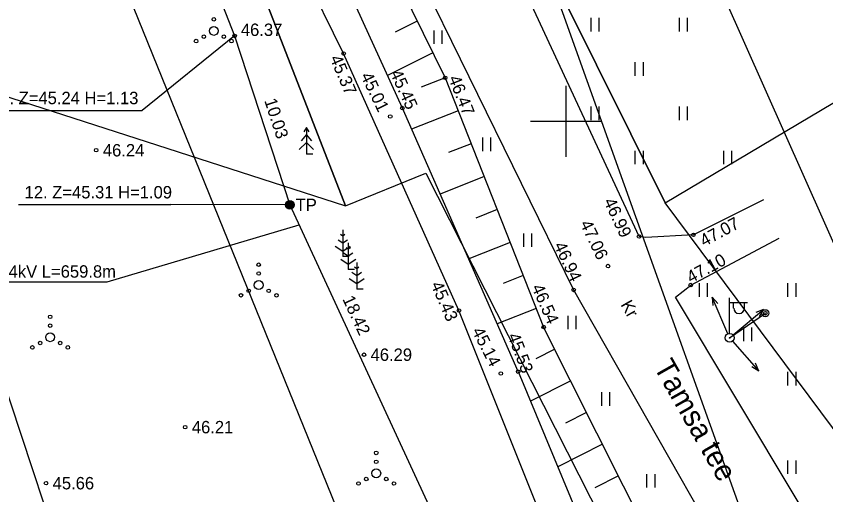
# Model space of a CAD drawing. Extents: x 642747 to 644424, y 6457048 to 6458238.
# Drawn here: x 644068.96 to 644114.68, y 6457678.92 to 6457705.93 of the extents above; entities that cross this region are included whole.
import ezdxf

# ---------------------------------------------------------------- set-up
doc = ezdxf.new("R2010")
doc.units = 0
for name, color, linetype in [('ABIJOONIS', 7, 'Continuous'), ('HALJASTUS', 7, 'Continuous'), ('JOONSIDE', 7, 'Continuous'), ('KOORDPUNKT', 7, 'Continuous'), ('KORGUS', 7, 'Continuous'), ('KPKAABEL', 7, 'Continuous'), ('KPOHULIIN', 7, 'Continuous'), ('MOOTPIIR', 7, 'Continuous'), ('MPOHULIIN', 7, 'Continuous'), ('PIIR', 7, 'Continuous'), ('POST', 7, 'Continuous'), ('PUU', 7, 'Continuous'), ('RELJEEF', 7, 'Continuous'), ('TEE', 7, 'Continuous'), ('VEEKOGU', 7, 'Continuous'), ('VORK', 7, 'Continuous'), ('VORMISTUS', 7, 'Continuous')]:
    doc.layers.add(name, color=color, linetype=linetype)

msp = doc.modelspace()

# ---------------------------------------------------------------- linework, layer by layer
at = {"layer": 'ABIJOONIS'}
msp.add_lwpolyline([(644048.392, 6457690.932), (644074.092, 6457690.932), (644084.942, 6457694.151)], dxfattribs=at)
at = {"layer": 'HALJASTUS'}
for p, q in [((644101.406, 6457705.833), (644101.406, 6457705.072)), ((644101.861, 6457705.833), (644101.861, 6457705.072)), ((644106.406, 6457705.833), (644106.406, 6457705.072)), ((644106.861, 6457705.833), (644106.861, 6457705.072)), ((644092.542, 6457705.127), (644092.542, 6457704.366)), ((644092.997, 6457705.127), (644092.997, 6457704.366)), ((644103.906, 6457703.333), (644103.906, 6457702.572)), ((644104.361, 6457703.333), (644104.361, 6457702.572)), ((644101.406, 6457700.833), (644101.406, 6457700.072)), ((644101.861, 6457700.833), (644101.861, 6457700.072)), ((644106.406, 6457700.833), (644106.406, 6457700.072)), ((644106.861, 6457700.833), (644106.861, 6457700.072)), ((644095.293, 6457699.079), (644095.293, 6457698.318)), ((644095.748, 6457699.079), (644095.748, 6457698.318)), ((644103.906, 6457698.333), (644103.906, 6457697.572)), ((644104.361, 6457698.333), (644104.361, 6457697.572)), ((644108.906, 6457698.333), (644108.906, 6457697.572)), ((644109.361, 6457698.333), (644109.361, 6457697.572)), ((644097.602, 6457693.676), (644097.602, 6457692.915)), ((644098.057, 6457693.676), (644098.057, 6457692.915)), ((644107.529, 6457690.856), (644107.529, 6457690.095)), ((644107.984, 6457690.856), (644107.984, 6457690.095)), ((644112.529, 6457690.856), (644112.529, 6457690.095)), ((644112.984, 6457690.856), (644112.984, 6457690.095)), ((644100.115, 6457689.021), (644100.115, 6457688.26)), ((644100.57, 6457689.021), (644100.57, 6457688.26)), ((644110.029, 6457688.356), (644110.029, 6457687.595)), ((644110.484, 6457688.356), (644110.484, 6457687.595)), ((644112.529, 6457685.856), (644112.529, 6457685.095)), ((644112.984, 6457685.856), (644112.984, 6457685.095)), ((644102.017, 6457684.706), (644102.017, 6457683.945)), ((644102.472, 6457684.706), (644102.472, 6457683.945)), ((644112.529, 6457680.856), (644112.529, 6457680.095)), ((644112.984, 6457680.856), (644112.984, 6457680.095)), ((644104.564, 6457680.085), (644104.564, 6457679.324)), ((644105.019, 6457680.085), (644105.019, 6457679.324))]:
    msp.add_line(p, q, dxfattribs=at)
for centre, radius in [((644080.121, 6457705.751), 0.1), ((644080.121, 6457705.101), 0.25), ((644079.121, 6457704.526), 0.1), ((644079.556, 6457704.776), 0.1), ((644080.686, 6457704.776), 0.1), ((644081.121, 6457704.526), 0.1), ((644082.659, 6457691.906), 0.1), ((644082.659, 6457691.406), 0.1), ((644082.659, 6457690.756), 0.25), ((644082.094, 6457690.431), 0.1), ((644083.224, 6457690.431), 0.1), ((644081.659, 6457690.181), 0.1), ((644083.659, 6457690.181), 0.1), ((644070.877, 6457688.962), 0.1), ((644070.877, 6457688.462), 0.1), ((644070.877, 6457687.812), 0.25), ((644069.877, 6457687.237), 0.1), ((644070.312, 6457687.487), 0.1), ((644071.442, 6457687.487), 0.1), ((644071.877, 6457687.237), 0.1), ((644089.295, 6457681.283), 0.1), ((644089.295, 6457680.783), 0.1), ((644089.295, 6457680.133), 0.25), ((644088.73, 6457679.808), 0.1), ((644089.86, 6457679.808), 0.1), ((644088.295, 6457679.558), 0.1), ((644090.295, 6457679.558), 0.1)]:
    msp.add_circle(centre, radius, dxfattribs=at)
at = {"layer": 'KOORDPUNKT'}
for p, q in [((644081.299, 6457704.816), (644076.077, 6457700.616)), ((644067.187, 6457700.616), (644076.077, 6457700.616)), ((644069.084, 6457695.297), (644077.694, 6457695.297)), ((644084.417, 6457695.285), (644077.694, 6457695.297))]:
    msp.add_line(p, q, dxfattribs=at)
for points in [[(644081.299, 6457704.816), (644081.299, 6457704.816), (644081.299, 6457704.816)], [(644084.417, 6457695.285), (644084.417, 6457695.285), (644084.417, 6457695.285)]]:
    msp.add_lwpolyline(points, dxfattribs=at)
at = {"layer": 'KORGUS'}
for centre in [(644081.299, 6457704.816), (644087.455, 6457703.827), (644093.19, 6457702.456), (644090.771, 6457700.745), (644090.086, 6457700.27), (644073.48, 6457698.367), (644104.136, 6457693.495), (644107.203, 6457693.592), (644102.385, 6457691.828), (644107.056, 6457690.755), (644100.441, 6457690.483), (644093.965, 6457689.322), (644111.269, 6457689.166), (644098.75, 6457688.389), (644088.6, 6457686.827), (644096.33, 6457685.764), (644097.313, 6457685.871), (644078.505, 6457682.738), (644070.645, 6457679.575)]:
    msp.add_circle(centre, 0.1, dxfattribs=at)
at = {"layer": 'KPKAABEL'}
msp.add_lwpolyline([(644063.341, 6457736.874), (644063.814, 6457738.243), (644064.085, 6457738.786), (644069.675, 6457740.685), (644070.251, 6457740.516), (644070.657, 6457739.804), (644071.702, 6457735.361), (644072.419, 6457732.308), (644073.692, 6457725.34), (644075.548, 6457720.26), (644079.636, 6457709.071), (644081.299, 6457704.816), (644084.417, 6457695.285), (644092.153, 6457678.564), (644095.564, 6457671.153), (644098.741, 6457664.129), (644103.079, 6457652.715), (644111.131, 6457630.665)], dxfattribs=at)
at = {"layer": 'KPOHULIIN'}
msp.add_lwpolyline([(644061.981, 6457739.913), (644094.239, 6457660.452), (644124.342, 6457586.031), (644125.691, 6457582.672)], dxfattribs=at)
at = {"layer": 'MOOTPIIR'}
msp.add_lwpolyline([(643525.446, 6457467.559), (643537.447, 6457435.458), (643944.848, 6457628.51), (644046.626, 6457529.09), (644067.022, 6457529.09), (644138.408, 6457598.401), (644075.1, 6457775.215), (644046.02, 6457752.582), (644092.466, 6457611.94), (644070.657, 6457576.375), (644041.981, 6457570.717), (643942.223, 6457662.862)], close=True, dxfattribs=at)
at = {"layer": 'MPOHULIIN'}
for p, q in [((644108.269, 6457690.079), (644108.309, 6457689.605)), ((644108.269, 6457690.079), (644108.584, 6457689.722)), ((644109.155, 6457688.01), (644108.269, 6457690.079)), ((644109.445, 6457687.941), (644111.172, 6457689.383)), ((644111.172, 6457689.383), (644110.73, 6457689.209)), ((644111.172, 6457689.383), (644110.921, 6457688.98)), ((644109.419, 6457687.593), (644110.908, 6457685.906)), ((644110.908, 6457685.906), (644110.722, 6457686.344)), ((644110.908, 6457685.906), (644110.498, 6457686.147))]:
    msp.add_line(p, q, dxfattribs=at)
at = {"layer": 'PIIR'}
for points in [[(644172.44, 6457634.51), (644128.57, 6457664.58), (644105.62, 6457695.4), (644084.27, 6457738.29), (644082.35, 6457742.69), (644071.37, 6457766.77), (644068.6, 6457772.82), (644052.27, 6457804.54)], [(644056.78, 6457779.28), (644062.47, 6457766.56), (644060.34, 6457762.97), (644041.41, 6457742.89), (644054.5, 6457738.54), (644058.72, 6457740.17), (644055.31, 6457749.58), (644061, 6457751.62), (644060.21, 6457753.82), (644065.16, 6457760.36), (644069.76, 6457744.43), (644073.59, 6457731.16), (644087.56, 6457695.23), (644092.09, 6457697.08), (644102.74, 6457676.12), (644108.68, 6457668.18), (644119.21, 6457655.5), (644137.18, 6457639.57)]]:
    msp.add_lwpolyline(points, dxfattribs=at)
for points in [[(644084.27, 6457738.29), (644105.62, 6457695.4), (644117.87, 6457702.68), (644141.47, 6457716.14), (644166.4, 6457723.98), (644161.44, 6457753.91), (644160.79, 6457756.77), (644152.83, 6457754.95), (644133.56, 6457751.83), (644087.35, 6457749.32), (644082.35, 6457742.69)], [(644073.59, 6457731.16), (644043.85, 6457709.33), (644087.56, 6457695.23)]]:
    msp.add_lwpolyline(points, close=True, dxfattribs=at)
at = {"layer": 'POST'}
for p, q in [((644109.254, 6457688.031), (644109.254, 6457690.031)), ((644109.254, 6457689.781), (644110.254, 6457689.781)), ((644109.48, 6457689.46), (644109.48, 6457689.781)), ((644110.093, 6457689.46), (644110.093, 6457689.781)), ((644109.254, 6457687.781), (644111.269, 6457689.166)), ((644109.254, 6457687.781), (644109.254, 6457687.781))]:
    msp.add_line(p, q, dxfattribs=at)
for centre, radius in [((644084.417, 6457695.285), 0.25), ((644084.417, 6457695.285), 0.225), ((644084.417, 6457695.285), 0.2), ((644084.417, 6457695.285), 0.175), ((644084.417, 6457695.285), 0.15), ((644084.417, 6457695.285), 0.125), ((644084.417, 6457695.285), 0.1), ((644084.417, 6457695.285), 0.075), ((644084.417, 6457695.285), 0.05), ((644084.417, 6457695.285), 0.025), ((644111.269, 6457689.166), 0.2), ((644109.254, 6457687.781), 0.25), ((644109.254, 6457687.781), 0.0234)]:
    msp.add_circle(centre, radius, dxfattribs=at)
msp.add_arc((644109.787, 6457689.46), 0.306, 180, 0, dxfattribs=at)
at = {"layer": 'PUU'}
for p, q in [((644085.351, 6457699.654), (644085.201, 6457699.404)), ((644085.501, 6457699.404), (644085.351, 6457699.654)), ((644085.351, 6457699.654), (644085.351, 6457698.154)), ((644085.351, 6457699.254), (644085.051, 6457698.904)), ((644085.651, 6457698.904), (644085.351, 6457699.254)), ((644085.351, 6457698.804), (644084.951, 6457698.404)), ((644085.751, 6457698.404), (644085.351, 6457698.804)), ((644085.711, 6457698.154), (644085.351, 6457698.154)), ((644087.404, 6457693.52), (644087.28, 6457693.603)), ((644087.404, 6457693.87), (644087.404, 6457692.37)), ((644087.529, 6457693.603), (644087.404, 6457693.52)), ((644087.404, 6457693.12), (644087.138, 6457693.298)), ((644087.671, 6457693.298), (644087.404, 6457693.12)), ((644087.715, 6457693.133), (644087.715, 6457691.633)), ((644086.98, 6457692.96), (644087.404, 6457692.677)), ((644087.404, 6457692.677), (644087.828, 6457692.96)), ((644087.715, 6457692.783), (644087.59, 6457692.866)), ((644087.839, 6457692.866), (644087.715, 6457692.783)), ((644087.291, 6457692.223), (644087.715, 6457691.94)), ((644087.764, 6457692.37), (644087.404, 6457692.37)), ((644087.715, 6457692.383), (644087.448, 6457692.561)), ((644087.982, 6457692.561), (644087.715, 6457692.383)), ((644087.715, 6457691.94), (644088.139, 6457692.223)), ((644088.191, 6457691.682), (644088.066, 6457691.764)), ((644088.191, 6457692.032), (644088.191, 6457690.532)), ((644088.315, 6457691.764), (644088.191, 6457691.682)), ((644088.075, 6457691.633), (644087.715, 6457691.633)), ((644088.191, 6457691.282), (644087.924, 6457691.459)), ((644088.457, 6457691.459), (644088.191, 6457691.282)), ((644087.766, 6457691.121), (644088.191, 6457690.838)), ((644088.191, 6457690.838), (644088.615, 6457691.121)), ((644088.551, 6457690.532), (644088.191, 6457690.532))]:
    msp.add_line(p, q, dxfattribs=at)
at = {"layer": 'RELJEEF'}
for p, q in [((644091.615, 6457705.655), (644090.356, 6457705.035)), ((644092.498, 6457703.86), (644089.927, 6457702.594)), ((644093.19, 6457702.456), (644091.834, 6457701.92)), ((644093.925, 6457700.596), (644091.293, 6457699.556)), ((644094.66, 6457698.736), (644093.38, 6457698.23)), ((644095.395, 6457696.876), (644092.905, 6457695.892)), ((644096.131, 6457695.016), (644094.921, 6457694.538)), ((644096.866, 6457693.156), (644094.517, 6457692.228)), ((644097.601, 6457691.297), (644096.462, 6457690.846)), ((644098.336, 6457689.437), (644096.128, 6457688.564)), ((644099.381, 6457687.133), (644098.308, 6457686.595)), ((644100.277, 6457685.345), (644098.005, 6457684.205)), ((644101.174, 6457683.557), (644099.974, 6457682.955)), ((644102.071, 6457681.769), (644099.543, 6457680.502)), ((644102.967, 6457679.982), (644101.64, 6457679.316))]:
    msp.add_line(p, q, dxfattribs=at)
for points in [[(644078.177, 6457735.139), (644082.441, 6457724.961), (644086.313, 6457716.42), (644093.19, 6457702.456), (644098.75, 6457688.389)], [(644112.377, 6457650.146), (644108.543, 6457663.96), (644104.761, 6457676.406), (644098.75, 6457688.389)]]:
    msp.add_lwpolyline(points, dxfattribs=at)
at = {"layer": 'TEE'}
for points in [[(644061.722, 6457771.823), (644064.397, 6457766.262), (644069.452, 6457755.916), (644076.842, 6457739.337), (644084.183, 6457724.283), (644091.562, 6457708.571), (644100.441, 6457690.483), (644108.831, 6457675.729), (644120.122, 6457661.417), (644128.409, 6457653.611)], [(644104.514, 6457693.442), (644104.136, 6457693.495), (644095.975, 6457711.092), (644088.251, 6457726.755), (644080.737, 6457740.751), (644073.333, 6457758.14), (644069.994, 6457765.435), (644069.979, 6457766.674)], [(644111.158, 6457695.559), (644107.203, 6457693.592), (644104.514, 6457693.442)], [(644123.504, 6457665.54), (644123.416, 6457665.621), (644113.131, 6457678.523), (644106.187, 6457690.082), (644107.056, 6457690.755), (644112.042, 6457693.41)]]:
    msp.add_lwpolyline(points, dxfattribs=at)
at = {"layer": 'VEEKOGU'}
for points in [[(644097.313, 6457685.871), (644090.771, 6457700.745), (644084.984, 6457713.434), (644079.553, 6457725.335), (644077.278, 6457732.291), (644077.554, 6457733.162)], [(644093.965, 6457689.322), (644087.455, 6457703.827), (644082.892, 6457713.097), (644079.401, 6457720.905), (644075.952, 6457728.576), (644074.141, 6457728.409), (644068.113, 6457723.971)], [(644108.124, 6457649.581), (644105.251, 6457659.448), (644102.028, 6457667.972), (644100.02, 6457674.182), (644093.965, 6457689.322)], [(644097.313, 6457685.871), (644102.294, 6457673.88), (644106.657, 6457660.328), (644109.969, 6457650.392)]]:
    msp.add_lwpolyline(points, dxfattribs=at)
at = {"layer": 'VORK'}
for p, q in [((644100, 6457702), (644100, 6457698)), ((644098, 6457700), (644102, 6457700))]:
    msp.add_line(p, q, dxfattribs=at)
at = {"layer": 'VORMISTUS'}
msp.add_line((644034.968, 6457873.554), (644180.435, 6457546.05), dxfattribs=at)

# ---------------------------------------------------------------- texts
at = {"layer": 'ABIJOONIS'}
msp.add_text('2040 M10-AJ Raadomi AHXAMK-W 3x120+35 24kV L=659.8m', height=0.7, dxfattribs=at).set_placement((644048.372, 6457691.174))
at = {"layer": 'JOONSIDE'}
for s, rotation, p in [('10.03', 288.1151, (644082.964, 6457701.173)), ('18.42', 294.8277, (644087.371, 6457689.971))]:
    msp.add_text(s, height=0.7, rotation=rotation, dxfattribs=at).set_placement(p)
at = {"layer": 'KOORDPUNKT'}
for s, p in [('11. Z=45.24 H=1.13', (644067.537, 6457700.966)), ('12. Z=45.31 H=1.09', (644069.434, 6457695.647))]:
    msp.add_text(s, height=0.7, dxfattribs=at).set_placement(p)
at = {"layer": 'KORGUS'}
for s, p in [('46.37', (644081.649, 6457704.816)), ('46.24', (644073.855, 6457698.017)), ('46.29', (644088.975, 6457686.477)), ('46.21', (644078.88, 6457682.388)), ('45.66', (644071.02, 6457679.225))]:
    msp.add_text(s, height=0.7, dxfattribs=at).set_placement(p)
for s, rotation, p in [(' 45.37', 292.9511, (644086.558, 6457703.806)), (' 45.45', 294.4314, (644089.954, 6457702.965)), (' 45.01', 295.8388, (644088.284, 6457702.8)), (' 46.47', 291.7899, (644093.261, 6457702.672)), (' 46.99', 295.2017, (644102.01, 6457695.715)), (' 47.07', 28.3147, (644107.583, 6457692.779)), (' 47.06', 295.476, (644100.674, 6457694.462)), (' 46.94', 294.9276, (644099.202, 6457693.24)), (' 47.10', 28.6484, (644106.838, 6457690.712)), (' 45.43', 293.5024, (644092.26, 6457691.022)), (' 46.54', 293.7697, (644097.949, 6457690.869)), (' 45.14', 296.8828, (644094.564, 6457688.4)), (' 45.53', 290.7738, (644096.609, 6457688.147))]:
    msp.add_text(s, height=0.7, rotation=rotation, dxfattribs=at).set_placement(p)
at = {"layer": 'POST'}
msp.add_text('TP', height=0.7, dxfattribs=at).set_placement((644084.743, 6457694.932))
at = {"layer": 'TEE'}
for s, height, p in [('Kr', 0.7, (644103.075, 6457689.655)), ('Tamsa tee', 1.2, (644104.938, 6457686.142))]:
    msp.add_text(s, height=height, rotation=299.6256, dxfattribs=at).set_placement(p)

doc.saveas('drawing.dxf')
